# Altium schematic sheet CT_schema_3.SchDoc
size 461 x 327 mm
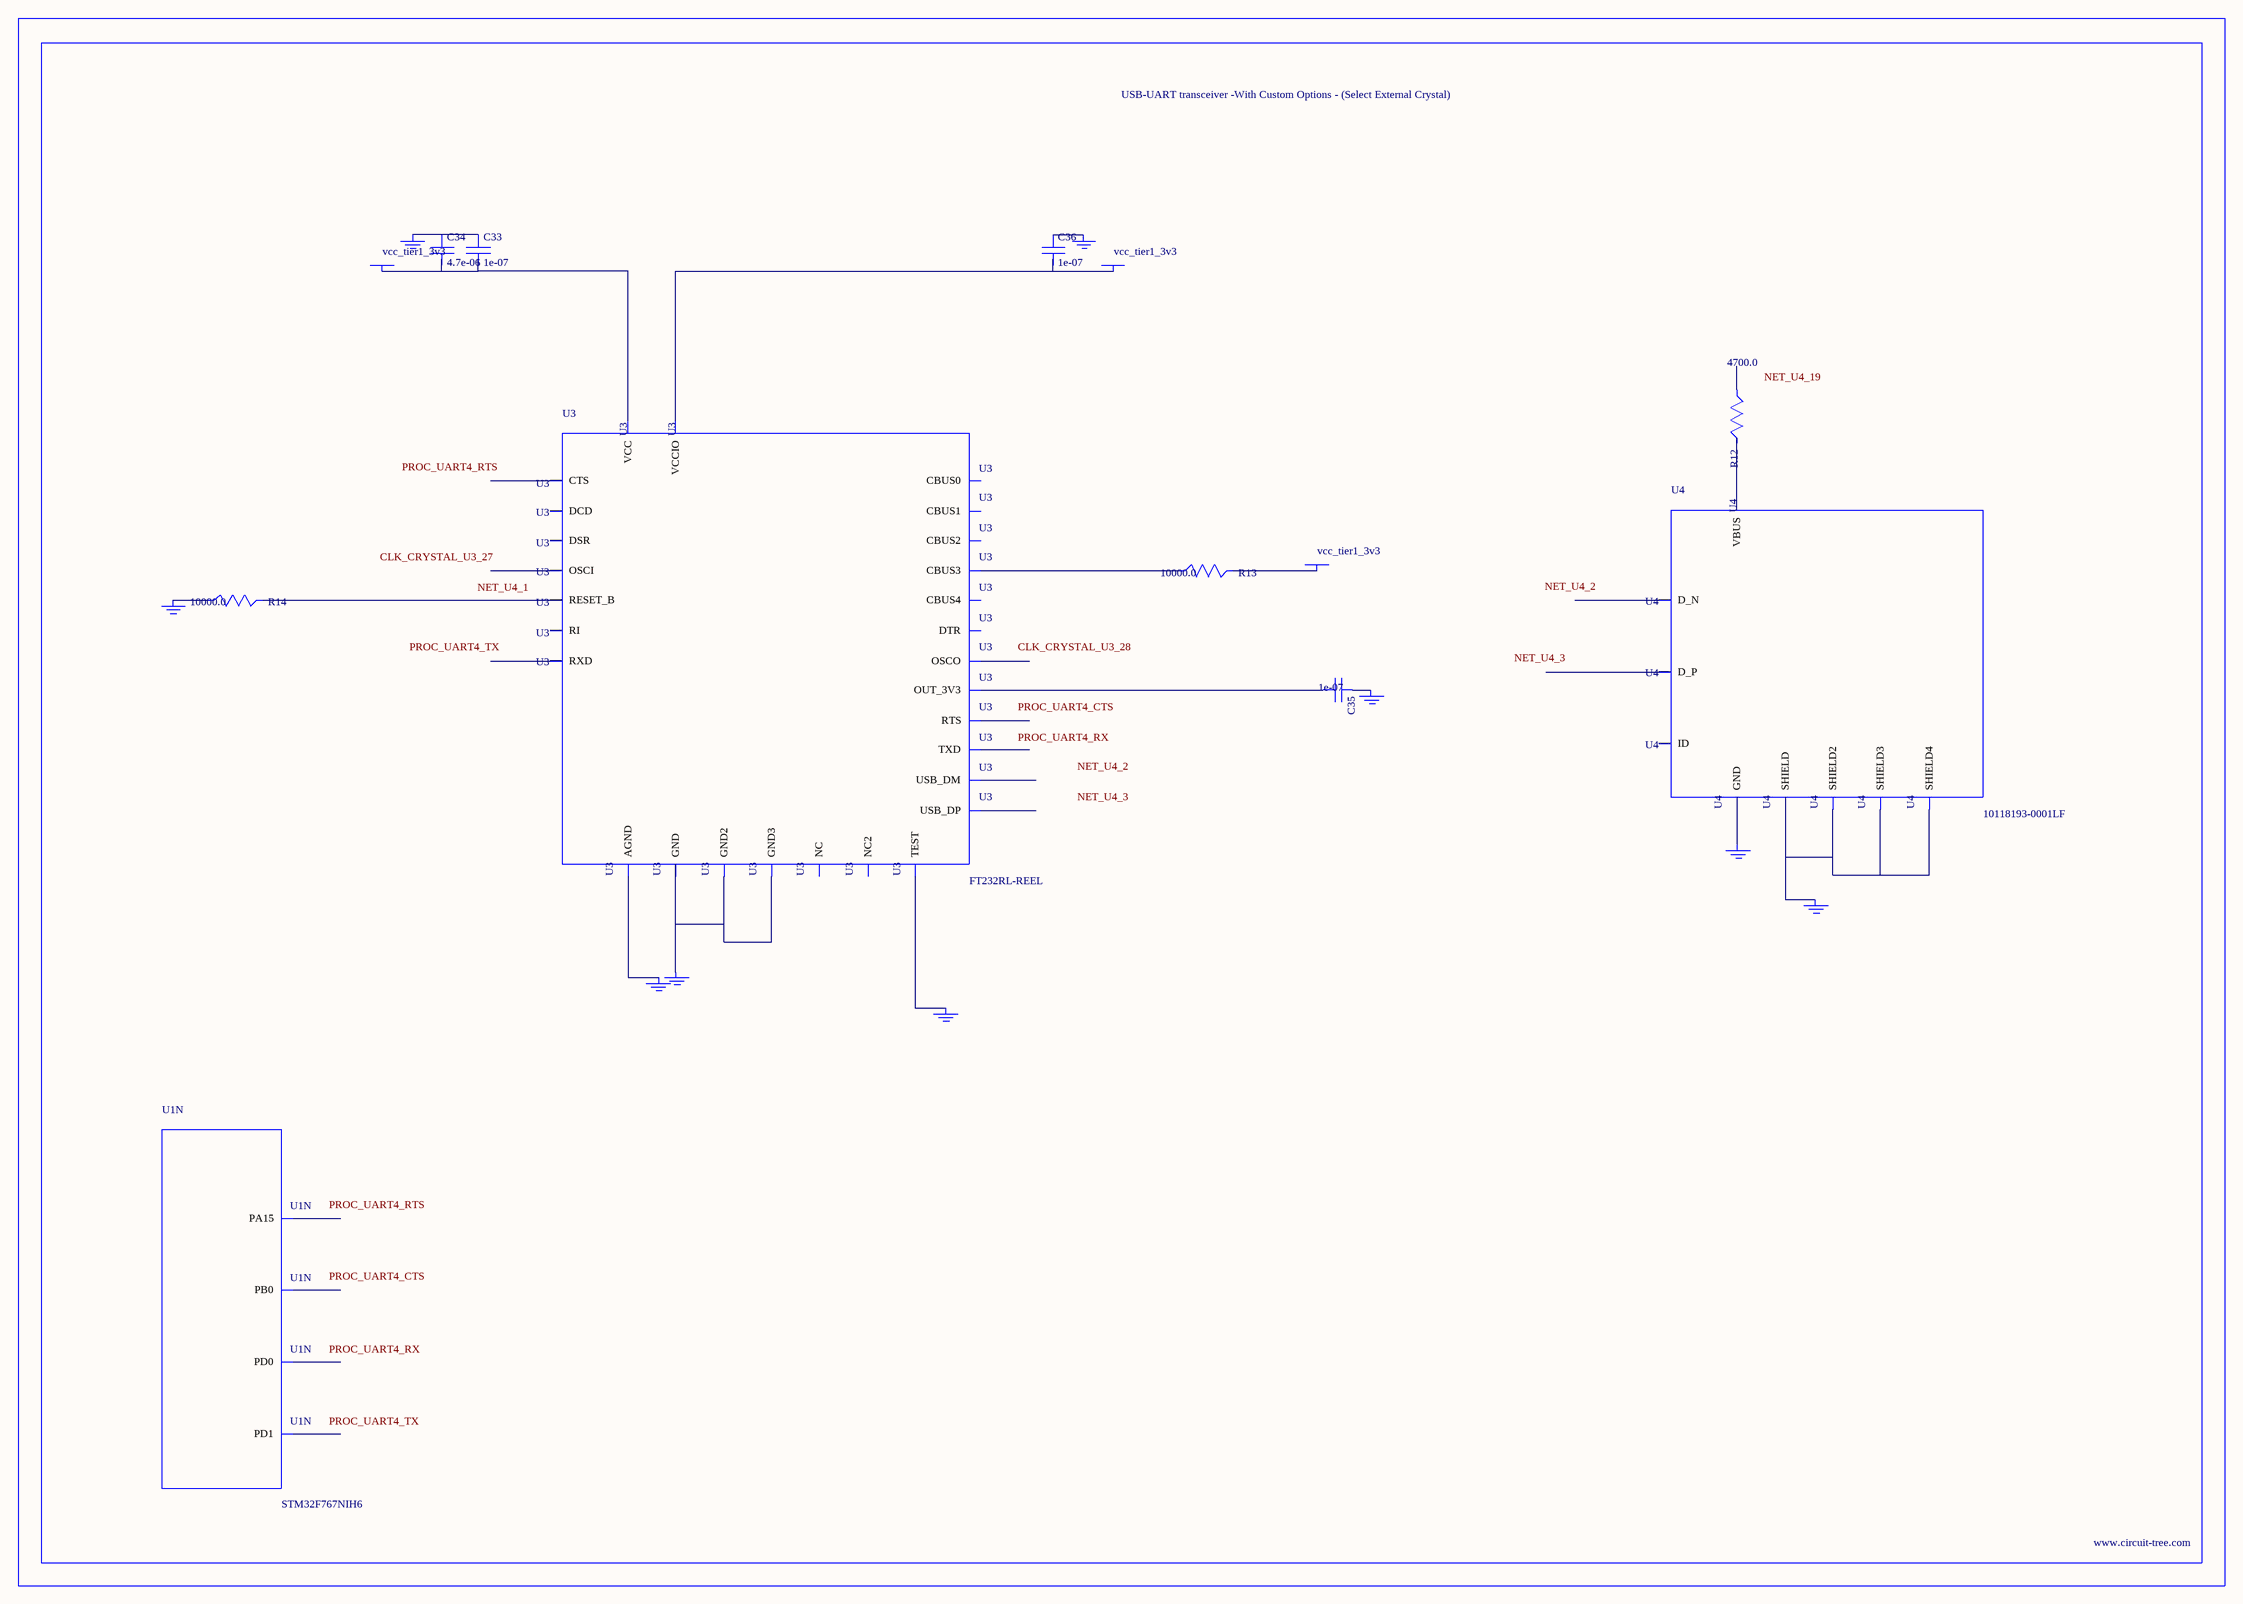
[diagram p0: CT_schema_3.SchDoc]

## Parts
BORDER2  (no value)
C33  1e-07  [C0402]
C34  4.7e-06  [C0805]
C35  1e-07  [C0402]
C36  1e-07  [C0402]
GND_INSTANCE_2_0  (no value)
GND_INSTANCE_2_1  (no value)
GND_INSTANCE_2_2  (no value)
GND_INSTANCE_2_3  (no value)
GND_INSTANCE_2_4  (no value)
GND_INSTANCE_2_5  (no value)
GND_INSTANCE_2_6  (no value)
GND_INSTANCE_2_7  (no value)
GND_INSTANCE_2_8  (no value)
POWER_INSTANCE_2_0  vcc_tier1_3v3
POWER_INSTANCE_2_1  vcc_tier1_3v3
POWER_INSTANCE_2_2  vcc_tier1_3v3
R12  4700.0  [R0603]
R13  10000.0  [R0603]
R14  10000.0  [R0603]
U1  STM32F767NIH6  [TFBGA216]  (part N of 16)
U3  FT232RL-REEL  [SSOP-28]
U4  10118193-0001LF  [FCI_10118193-0001LF]

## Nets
NetC33_1: C33.1 C34.1 GND_INSTANCE_2_3.0(GND)
NetC33_2: C33.2 C34.2 POWER_INSTANCE_2_2.0(PWR) U3.20(VCC)
NetC35_1: C35.1 GND_INSTANCE_2_1.0(GND)
NetC35_2: C35.2 U3.17(OUT_3V3)
NetC36_1: C36.1 GND_INSTANCE_2_0.0(GND)
NetC36_2: C36.2 POWER_INSTANCE_2_0.0(PWR) U3.4(VCCIO)
NetGND_INSTANCE_2_2_0: GND_INSTANCE_2_2.0(GND) R14.1
NetGND_INSTANCE_2_4_0: GND_INSTANCE_2_4.0(GND) U3.25(AGND)
NetGND_INSTANCE_2_5_0: GND_INSTANCE_2_5.0(GND) U3.26(TEST)
NetGND_INSTANCE_2_6_0: GND_INSTANCE_2_6.0(GND) U3.7(GND) U3.18(GND2) U3.21(GND3)
NetGND_INSTANCE_2_7_0: GND_INSTANCE_2_7.0(GND) U4.6(SHIELD) U4.7(SHIELD2) U4.8(SHIELD3) U4.9(SHIELD4)
NetGND_INSTANCE_2_8_0: GND_INSTANCE_2_8.0(GND) U4.5(GND)
NetPOWER_INSTANCE_2_1_0: POWER_INSTANCE_2_1.0(PWR) R13.2
NetR12_2: R12.2 U4.1(VBUS)
NetR13_1: R13.1 U3.14(CBUS3)
NetR14_2: R14.2 U3.19(RESET_B)

Not connected (* = marked no-connect by the designer): R12 1; U1 A13(PA15) B12(PD0) C12(PD1) R5(PB0); U3 1(TXD) 2(DTR) 3(RTS) 5(RXD) 6(RI) 8(NC) 9(DSR) 10(DCD) 11(CTS) 12(CBUS4) 13(CBUS2) 15(USB_DP) 16(USB_DM) 22(CBUS1) 23(CBUS0) 24(NC2) 27(OSCI) 28(OSCO); U4 2(D_N) 3(D_P) 4(ID)

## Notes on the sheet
- Labels drawn without touching a wire or pin: CLK_CRYSTAL_U3_27, CLK_CRYSTAL_U3_28, NET_U4_1, NET_U4_2, NET_U4_3, NET_U4_19, PROC_UART4_CTS, PROC_UART4_RTS, PROC_UART4_RX, PROC_UART4_TX

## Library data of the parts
BORDER2 = BORDER_PAGE2
C33 C35 C36 = C0402C104K3RACTU
C34 = C0805C475K4RACTU
GND_INSTANCE_2_0-GND_INSTANCE_2_8 = GND
POWER_INSTANCE_2_0-POWER_INSTANCE_2_2 = PWR
R12 = RC0603JR-074K7L
R13 R14 = RC0603JR-0710KL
